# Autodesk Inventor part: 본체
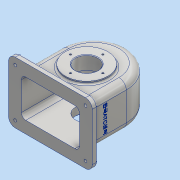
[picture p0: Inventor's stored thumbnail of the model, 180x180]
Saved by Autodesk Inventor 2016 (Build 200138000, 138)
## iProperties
Created: 2018-11
Part Number: 본체
Material: 알루미늄 6061
Document SubType Name: Modeling
Designer: user
Mass: 1092.35 g
Surface Area: 1180.61 cm^2
Volume: 404.572 cm^3
Density: 2.7 g/cm^3
Appearance: 알루미늄 - 평지
Author: user
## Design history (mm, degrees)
sketch "스케치3"
  geometry: L1 (75, 55)-(-75, 55); L2 (-75, 55)-(-75, -55); L3 (-75, -55)-(75, -55); L4 (75, -55)-(75, 55); L5 (75, 55)-(-75, -55); L6 (-75, 55)-(75, -55); 1 further point
  constraints: 12 end point, 2 midpoint, 2 parallel, 1 horizontal, 1 perpendicular
  dimensions: "d3" = 110 distance of L3.end L1.start; "d4" = 150 distance of L2.end L3.end
extrude "돌출1" new body sketch "스케치3" distance "d5" = 10; taper "d6" = 0 deg
sketch "스케치4"
  geometry: L1 (-75, 0)-(75, 0) reference; L2 (-75, 10)-(75, 10) reference; L3 (-58, 78)-(-58, 10); L4 (58, 78)-(58, 10); A1 r 58 centre (0, 78) between (-58, 78) and (58, 78); 2 further points
  constraints: 4 end point, 2 perpendicular, 2 point on circle, 2 point on line, 2 tangent, 1 centre point, 1 midpoint, 1 vertical alignment
  dimensions: "d7" = 116 diameter of A1; "d11" = 136 dimension on A1 L1
extrude "돌출2" join sketch "스케치4" stored distance "d12" = 77; taper "d13" = 0 deg
feature "쉘1" dims "d16" = 10, "d17" = 5, "d30" = 6
sketch "스케치6"
  geometry: L1 (-75, 0)-(75, 0) reference; C1 r 38 at (0, 65); 2 further points
  constraints: 1 centre point, 1 midpoint, 1 vertical alignment
  dimensions: "d18" = 65 distance from line of L1 C1.centre; "d19" = 76 diameter of C1
extrude "돌출3" join sketch "스케치6" distance "d20" = 5; taper "d21" = 0 deg
node "작업 평면2"
sketch "스케치12"
  geometry: L1 (52, -78)-(-52, -78) reference; C1 r 28 at (0, -13); 2 further points
  constraints: 1 centre point, 1 midpoint, 1 vertical alignment
  dimensions: "d36" = 65 distance from line of L1 C1.centre; "d37" = 56 diameter of C1
extrude "돌출7" join sketch "스케치12" distance "d38" = 14; taper "d39" = 40 deg
sketch "스케치13"
  geometry: C1 r 20 at (0, 0); C2 r 38 at (0, 0) reference; 1 further point
  constraints: 1 centre point, 1 concentric
  dimensions: "d40" = 40 diameter of C1
extrude "돌출8" cut sketch "스케치13" distance "d41" = 24; taper "d42" = 0 deg
node "작업 평면3"
sketch "스케치14"
  geometry: C1 r 6 at (0, 0); 1 further point
  constraints: 1 centre point, 1 coincident
  dimensions: "d44" = 12 diameter of C1
extrude "돌출9" join sketch "스케치14" stored distance "d45" = 24; taper "d46" = 5 deg
sketch "스케치17"
  geometry: 1 further point
hole "구멍3" sketch "스케치17" at (0, 0) diameter "d62" = 4.459; stored, may be unused: countersink angle "d66" = 90 deg, drill point angle "d68" = 118 deg; dims "d63" = 20, "d64" = 4, "d65" = 2, "d67" = 12.8
sketch "스케치18"
  geometry: L1 (75, -55)-(75, 55) reference; L2 (-75, -55)-(75, -55) reference; C1 r 6 at (63, -43); 1 further point
  constraints: 1 centre point
  dimensions: "d72" = 12 distance from line of C1.centre L1; "d73" = 12 distance from line of L2 C1.centre; "d74" = 12 diameter of C1
extrude "돌출10" cut sketch "스케치18" distance "d75" = 4; taper "d76" = 0 deg
sketch "스케치19"
  geometry: C1 r 2.5 at (63, -43); C2 r 6 at (63, -43) reference; 1 further point
  constraints: 1 centre point, 1 concentric
  dimensions: "d77" = 5 diameter of C1
extrude "돌출11" cut sketch "스케치19" distance "d78" = 10; taper "d79" = 0 deg
fillet "모깎기1" dims "d86" = 12
fillet "모깎기2" dims "d87" = 3
fillet "모깎기3" dims "d88" = 13
fillet "모깎기4" dims "d89" = 3
fillet "모깎기5" dims "d90" = 3
fillet "모깎기6" dims "d91" = 8
sketch "스케치20"
  geometry: L1 (-17.5, -78)-(68.5, -78) reference; L2 (-13, 0)-(-13, -65) reference; 2 further points
  constraints: 1 other
  dimensions: "d92" = 40 distance from line of L1 point (25.5, -38); "d93" = 38.5 distance from line of L2 point (25.5, -38)
feature "엠보싱1" sketch "스케치20" dims "d16" = 10, "d17" = 5, "d30" = 6, "d94" = 0.5, "d95" = 0
sketch "스케치21"
  geometry: L1 (-63, 0)-(63, 0) reference; C1 r 38 at (0, 65); 2 further points
  constraints: 1 centre point, 1 midpoint, 1 vertical alignment
  dimensions: "d96" = 65 distance from line of L1 C1.centre; "d97" = 76 diameter of C1
extrude "돌출12" join sketch "스케치21" distance "d98" = 10; taper "d99" = 0 deg
sketch "스케치22"
  geometry: C1 r 20 at (0, 0); C2 r 38 at (0, 0) reference; 1 further point
  constraints: 1 centre point, 1 concentric
  dimensions: "d100" = 40 diameter of C1
extrude "돌출13" cut sketch "스케치22" distance "d101" = 18.5; taper "d102" = 0 deg
sketch "스케치23"
  geometry: C1 r 20 at (0, 0) reference; 2 further points
  constraints: 1 vertical alignment
  dimensions: "d103" = 29 distance of C1.centre point (0, 29)
hole "구멍4" sketch "스케치23" at (0, 29) diameter "d104" = 3.242; stored, may be unused: countersink angle "d108" = 90 deg, drill point angle "d110" = 118 deg; dims "d105" = 8, "d106" = 4, "d107" = 2, "d109" = 10
chamfer "모따기1" distance "d114" = 1; stored, may be unused: second distance "d115" = 2, angle "d116" = 45 deg
fillet "모깎기7" dims "d117" = 3
sketch "스케치24"
  geometry: C1 r 38 at (0, 0) reference; 2 further points
  constraints: 1 vertical alignment
  dimensions: "d118" = 29 distance of C1.centre point (0, 29)
hole "구멍5" sketch "스케치24" at (0, 29) diameter "d119" = 3.242; stored, may be unused: countersink angle "d123" = 90 deg, drill point angle "d125" = 118 deg; dims "d120" = 8, "d121" = 4, "d122" = 2, "d124" = 10
node "솔리드1"
pattern_linear "직사각형 패턴1" dims "d82" = 86, "d85" = 126
pattern_circular "원형 패턴2" dims angle "d112" = 360 deg
pattern_circular "원형 패턴3" dims angle "d127" = 360 deg
other parameters: "d35" = 14, "d43" = 142
